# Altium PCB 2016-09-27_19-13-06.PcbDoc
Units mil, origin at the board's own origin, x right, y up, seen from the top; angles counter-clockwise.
Board outline 3075 x 1501 mil, 4 copper layers (Top Layer, MidLayer1, MidLayer2, Bottom Layer); 18 components, 10 nets, 43 pads, 143 vias.
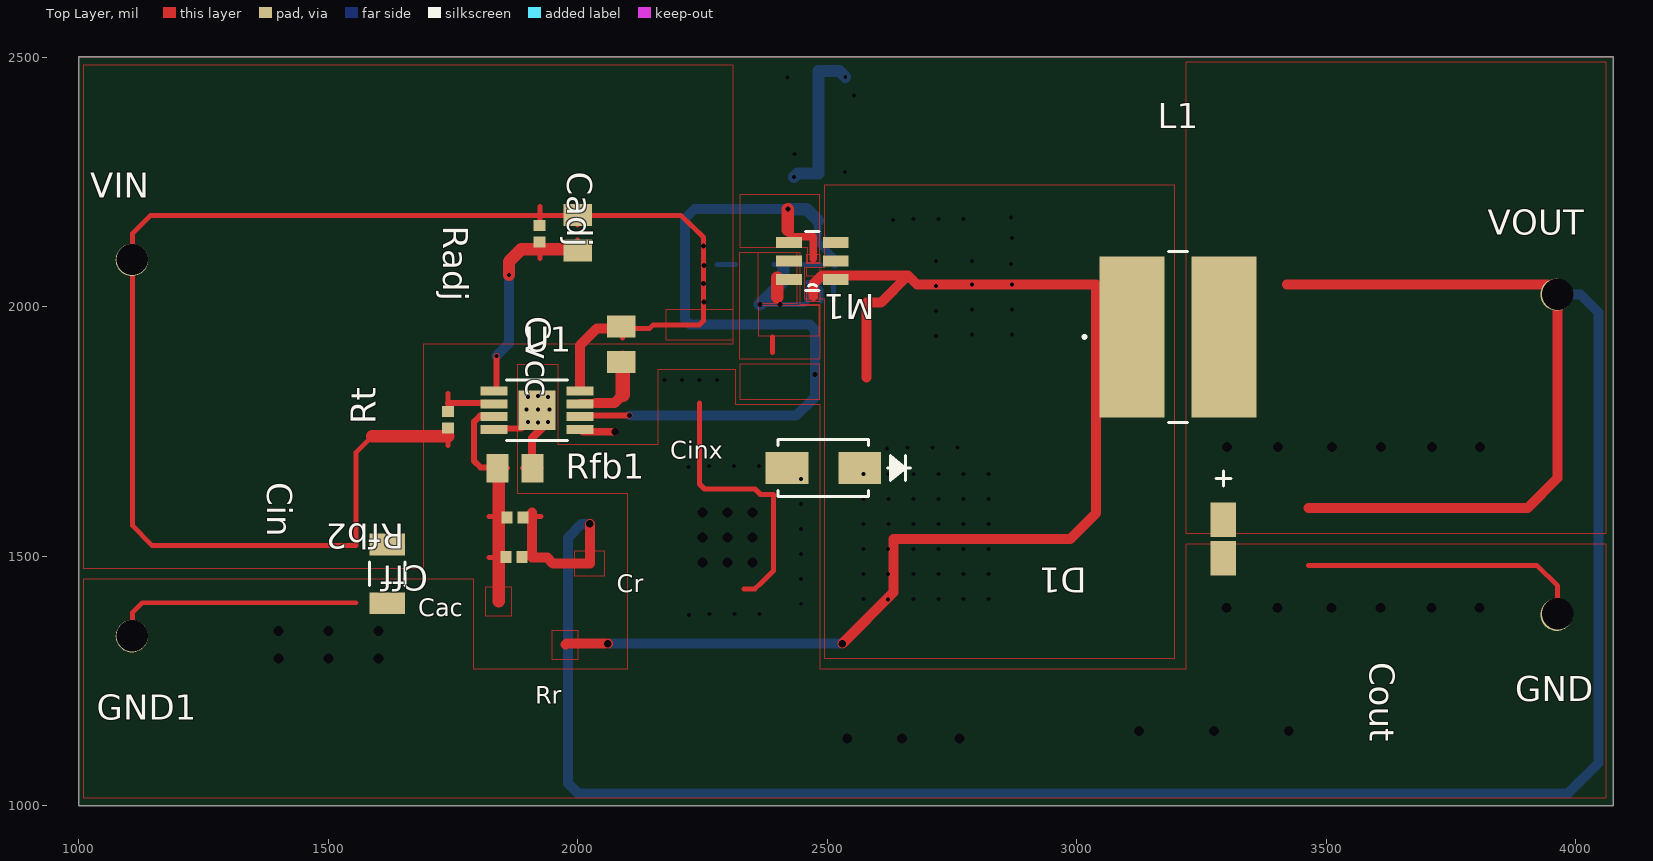
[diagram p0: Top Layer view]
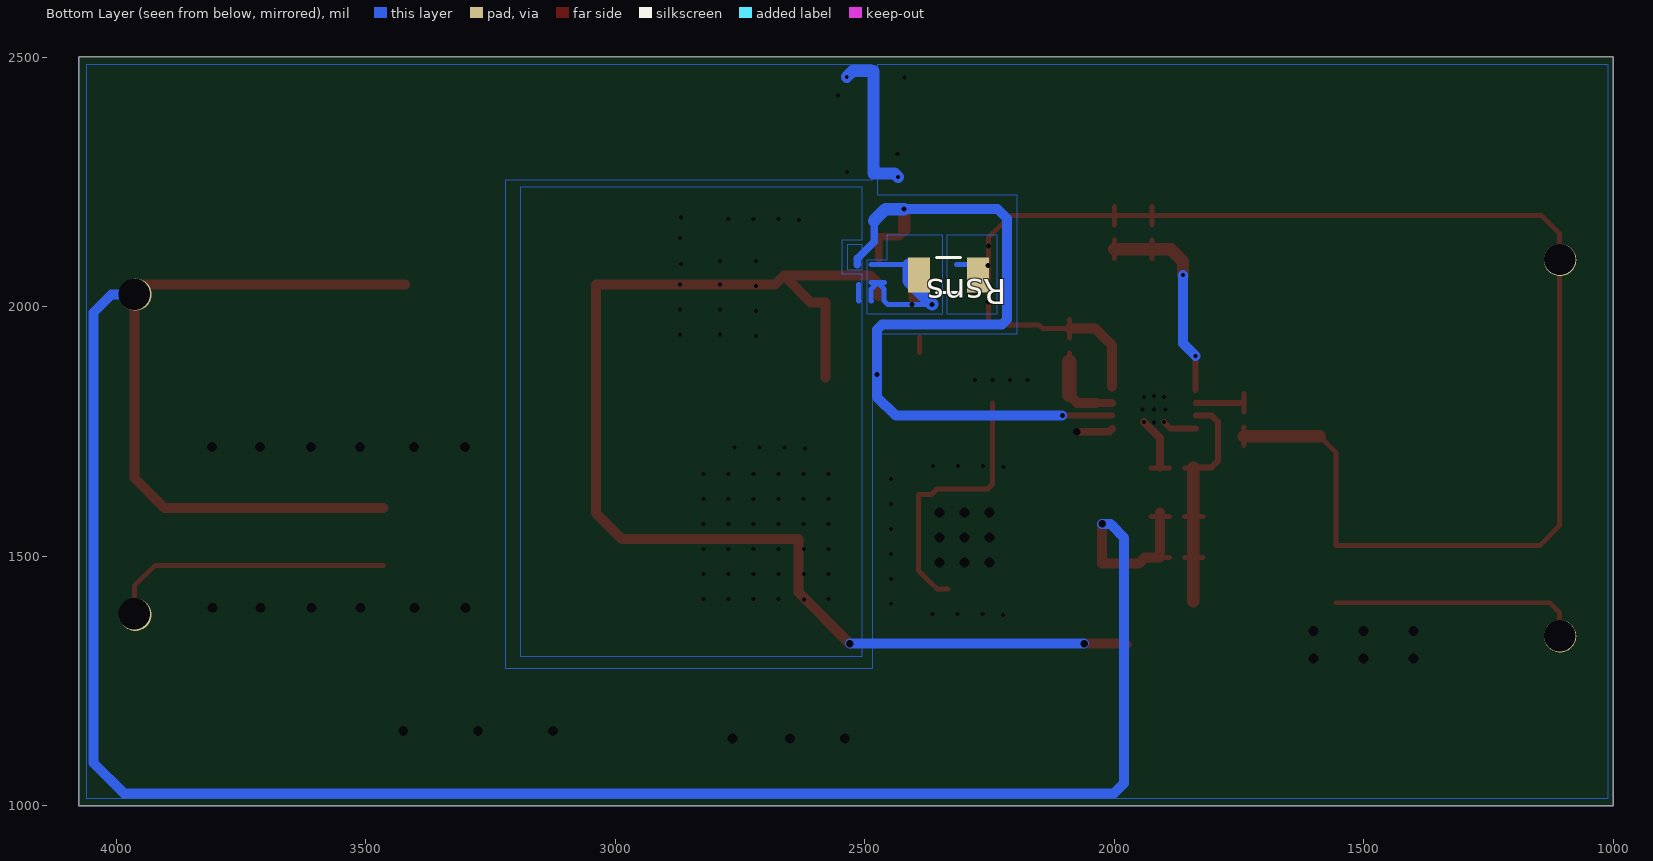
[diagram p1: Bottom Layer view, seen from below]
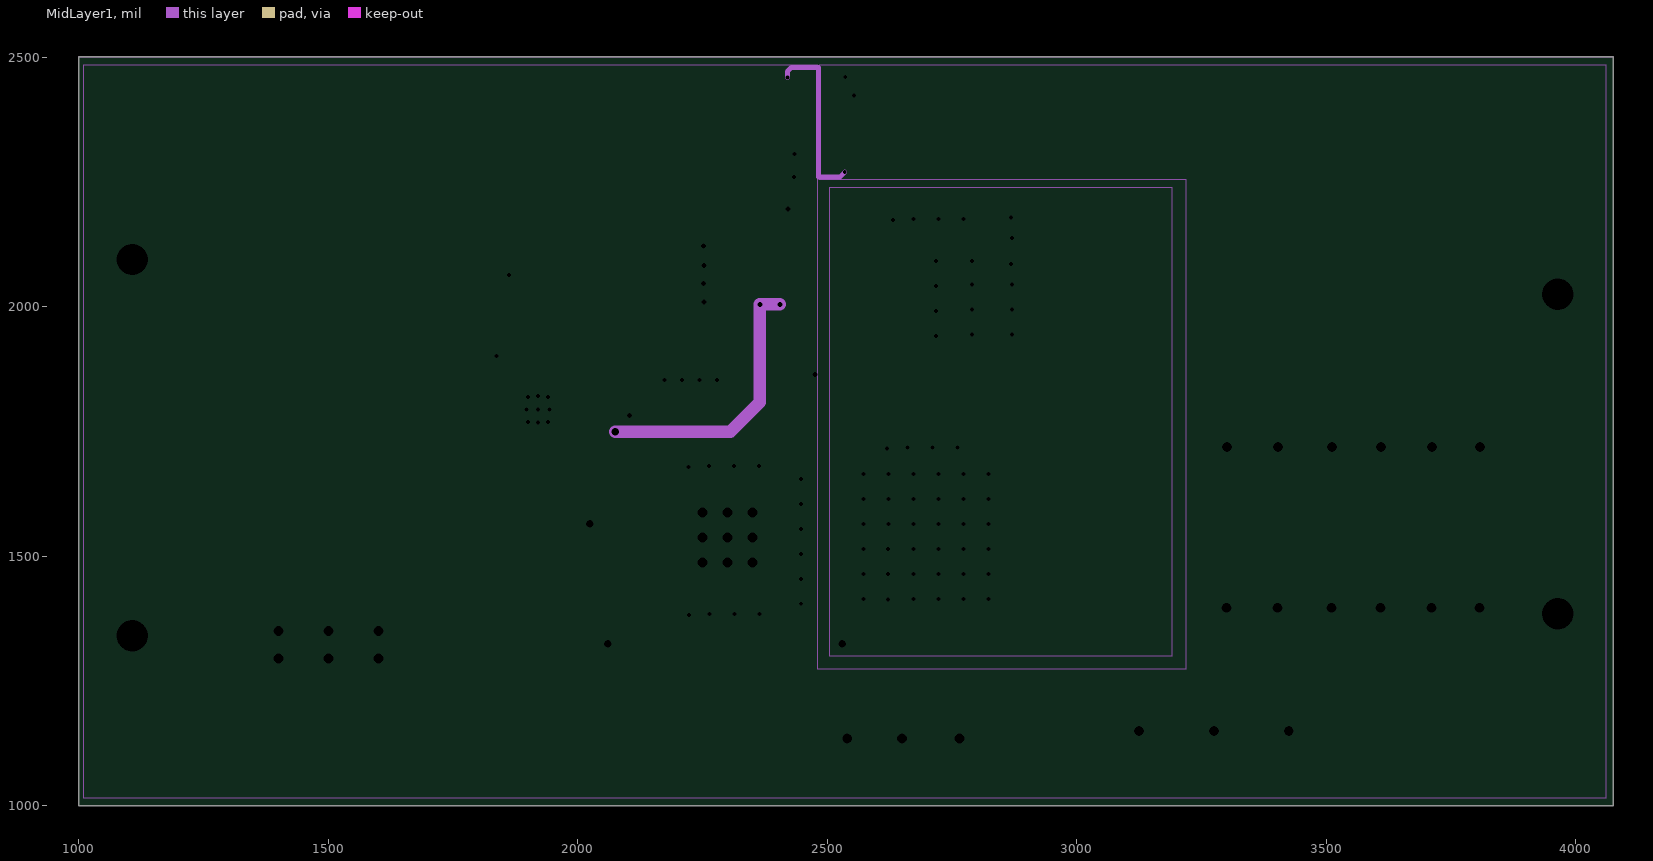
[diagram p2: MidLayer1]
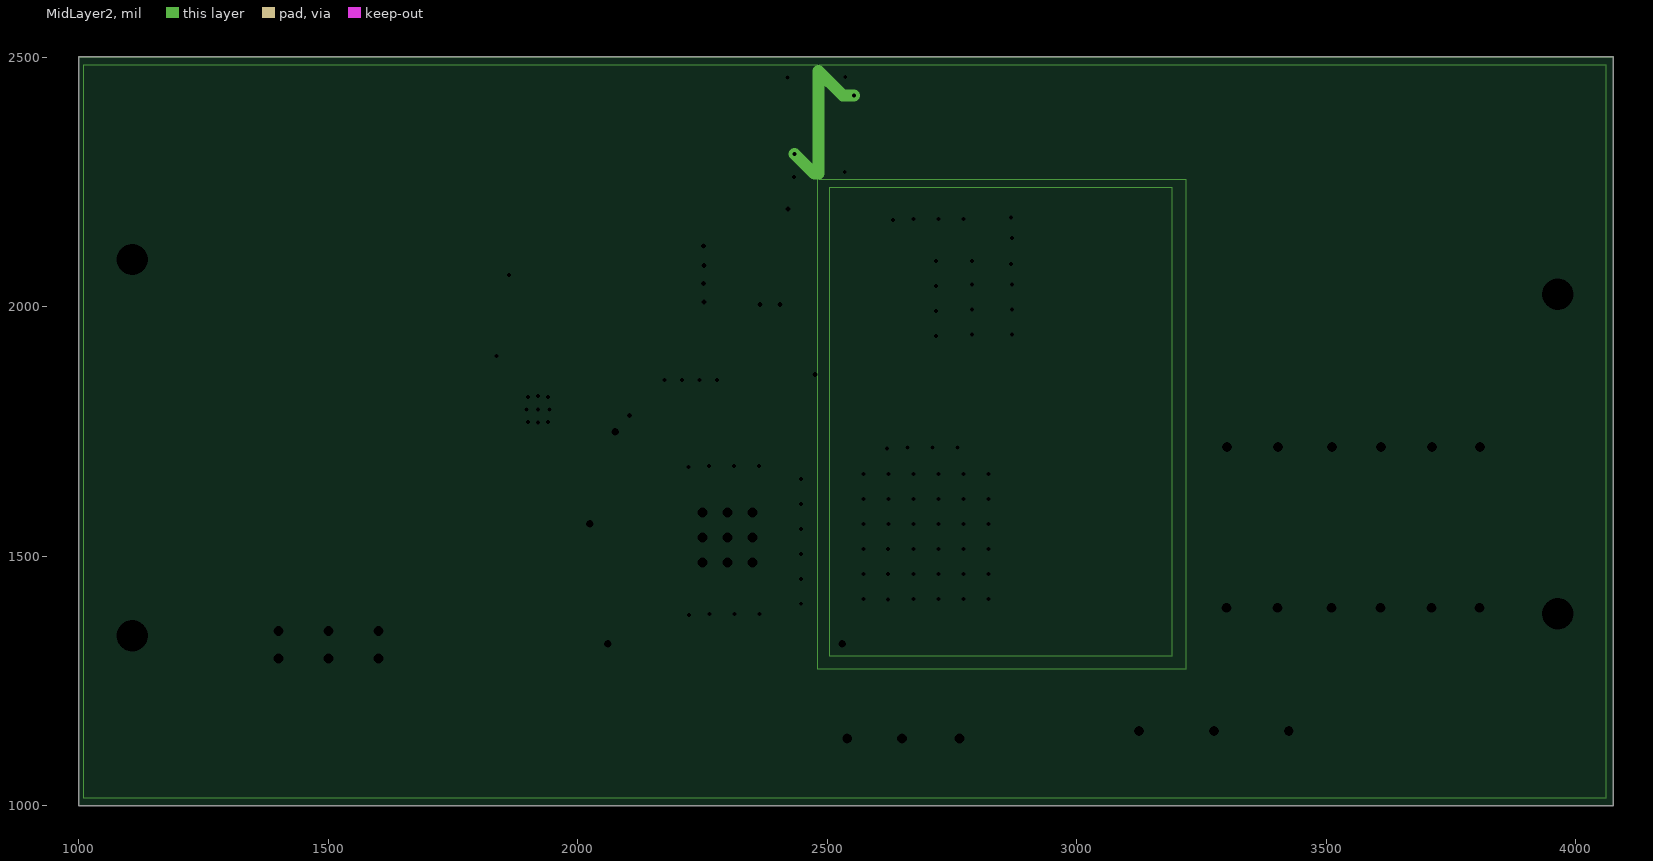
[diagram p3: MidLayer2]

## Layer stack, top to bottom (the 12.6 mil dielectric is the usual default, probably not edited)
Top Layer: signal copper 1.4
Dielectric: core 12.6, FR-4, Dk 4.8
MidLayer1: signal copper 1.4
Dielectric: prepreg 12.6, FR-4, Dk 4.8
MidLayer2: signal copper 1.4
Dielectric: core 12.6, FR-4, Dk 4.8
Bottom Layer: signal copper 1.4

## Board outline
1000,1000 4075,1000 4075,2501 1000,2501

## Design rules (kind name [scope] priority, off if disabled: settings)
PlaneConnect [All] p0: scope1count=1 scope1_0_kind=Board scope1_0_value=Board scope2count=1 scope2_0_kind=Board scope2_0_value=Board commentlength=0 planeconnectstyle=Direct reliefexpansion=20 reliefentries=4 reliefconductorwidth=10 reliefairgap=10
PlaneConnect [All] p1: planeconnectstyle=Direct reliefexpansion=20 reliefentries=4 reliefconductorwidth=10 reliefairgap=10
PolygonConnect [All] p0: scope1count=1 scope1_0_kind=Board scope1_0_value=Board scope2count=1 scope2_0_kind=Board scope2_0_value=Board commentlength=0 connectstyle=Direct reliefconductorwidth=10 reliefentries=4 polygonreliefangle="90 Angle"
PolygonConnect [All] p1: connectstyle=Direct reliefconductorwidth=10 reliefentries=4 polygonreliefangle="90 Angle"

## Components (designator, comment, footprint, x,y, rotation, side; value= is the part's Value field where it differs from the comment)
Cadj "" 0805 2000,2149 r270 top
Cff "" 0402 1872,1499 r180 top
Cin "" 1206_190 1618,1465 r270 top
Cout "" 3216-18 3294,1535 r270 top
Cvcc "" 0805 2087,1925 r270 top
D1 "" SMA 2492,1677 r180 top
GND "" TP-1502 3962,1383 r0 top
GND1 "" TP-1502 1106,1340 r0 top
L1 "" VLP8040 3203,1940 r0 top
M1 "" SOT-23-6 2470,2092 r180 top
Radj "" 0402 1923,2147 r270 top
Rfb1 "" 0805 1874,1677 r0 top
Rfb2 "" 0402 1874,1578 r180 top
Rsns "" 1206 2332,2064 r180 bottom
Rt "" 0402 1740,1774 r90 top
U1 "" MUY08A 1918,1793 r0 top
VIN "" TP-1502 1106,2094 r0 top
VOUT "" TP-1502 3962,2025 r0 top

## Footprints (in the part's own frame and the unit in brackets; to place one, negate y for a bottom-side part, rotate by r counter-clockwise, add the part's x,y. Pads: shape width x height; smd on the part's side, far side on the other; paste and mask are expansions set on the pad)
0402 [mil]
  rect 22x24 smd: 1(-16.5,0) 2(16.5,0)
0805 [mil]
  rect 44x57 smd: 1(-35.5,0) 2(35.5,0)
1206 [mil]
  rect 44x71 smd: 1(59,0) 2(-59,0)
  silkscreen extent -24,-36 24,36
1206_190 [mil]
  rect 44x71 smd: 1(-59,0) 2(59,0)
  silkscreen extent -24,-36 24,36
3216-18 [mil]
  rect 69x51 smd: 1(-38.5,0) 2(38.5,0)
  silkscreen extent -136,-15 -106,15
MUY08A [mil]
  rect 54x18 smd: 1(-86.5,38.39) 2(-86.5,12.8) 3(-86.5,-12.8) 4(-86.5,-38.39) 5(86.5,-38.39) 6(86.5,-12.8) 7(86.5,12.8) 8(86.5,38.39)
  rect 74x79 smd: 9(0,0)
  silkscreen extent -61,-61 61,61
SMA [mil]
  rect 86x64 smd: 1(-73,0) 2(73,0)
  silkscreen extent -174,-58 90,58
SOT-23-6 [mil]
  rect 52x22 smd: 1(-47,37.4) 2(-47,0) 3(-47,-37.4) 4(47,-37.4) 5(47,0) 6(47,37.4)
  silkscreen extent -13,-59 13,59
TP-1502 [mil]
  round 65 / inner round 0 / far side round 65 hole 32: 1(0,0)
VLP8040 [mil]
  rect 130x323 smd: 1(-92.5,0) 2(92.5,0)
  silkscreen extent -190,-172 19,172

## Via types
v1: diameter 0, hole 8, Top Layer to Bottom Layer, 93 vias
v2: diameter 0, hole 20, Top Layer to Bottom Layer, 33 vias
v3: diameter 0, hole 10, Top Layer to Bottom Layer, 9 vias
v4: diameter 0, hole 15, Top Layer to Bottom Layer, 4 vias
v5: diameter 0, hole 63, Top Layer to Bottom Layer, 4 vias

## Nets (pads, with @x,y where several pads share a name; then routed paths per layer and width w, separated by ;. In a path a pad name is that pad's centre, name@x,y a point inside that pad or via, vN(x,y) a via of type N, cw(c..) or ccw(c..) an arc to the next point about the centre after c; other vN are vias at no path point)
0: Cin.2 Cout.2 D1.2 GND1.1 GND.1 Rfb1.2 U1.4 U1.9 | length 2864.1
  Top Layer w10: v5(1107,1341) 1107,1387 1127,1407 1555,1407 ; Rfb1.2@1889,1677.5 Rfb1.2@1926,1677.5 ; 2244,1807 2244,1645 2254,1635 2333,1635 2355,1635 2366,1624 2392,1624 2392,1471 2366,1445 2355,1435 2333,1435 ; 3465,1482 3922,1482 3964,1441 v5(3964,1385)
  Top Layer w12: U1.4@1836,1756 1887,1756 v1(1900,1769)
  Top Layer w16: Rfb1.2@1908,1678 1908,1737 v1(1940,1769)
  MidLayer1 w10: v1(2420,2460) 2420,2472 2428,2480 2482,2480 2482,2260 2525,2260 v1(2535,2270)
  MidLayer2 w24: v1(2434,2307) 2474,2267 2482,2267 2482,2473 2531,2424 v1(2554,2424)
  Bottom Layer w24: v1(2433,2260) 2440,2267 2482,2267 2482,2473 2524,2473 v1(2536,2461)
  other v1: 2223,1382 2264,1384 2314,1384 2364,1384 2447,1405 2447,1455 2447,1505 2447,1555 2447,1605 2447,1655 2222,1679 2263,1681 2313,1681 2363,1681 1920,1768 1897,1794 1920,1794 1943,1794 1900,1819 1940,1819 1920,1821 2174,1854 2209,1854 2244,1854 2279,1854
  other v2: 2540,1135 2650,1135 2765,1135 3125,1150 3275,1150 3425,1150 1400,1295 1500,1295 1600,1295 1400,1350 1500,1350 1600,1350 3300,1397 3402,1397 3511,1397 3609,1397 3711,1397 3807,1397 2250,1488 2300,1488 2350,1488 2250,1538 2300,1538 2350,1538 2250,1588 2300,1588 2350,1588
1: Cff.2 Rfb1.1 Rfb2.2 U1.3 | length 561.4
  Top Layer w10: 1822,1497.5 Cff.2@1859,1497.5 ; 1822,1579.5 Rfb2.2@1859,1579.5 ; Rfb1.1@1822,1677.5 Rfb1.1@1859,1677.5
  Top Layer w12: U1.3@1836,1782 1804,1782 1792,1770 1792,1691 1805,1678 Rfb1.1@1841,1678
  Top Layer w25: 1841,1410 1841,1498 Rfb1.1@1841,1678
2: Rt.2 U1.2 | length 134
  Top Layer w10: Rt.2@1739.5,1789 1739.5,1826 ; 1740,1807 1740,1808
  Top Layer w12: 1740,1807 U1.2@1836,1807
3: Cadj.1 Cin.1 Cvcc.1 Radj.1 Rsns.1 Rt.1 U1.8 VIN.1 | length 3315.7
  Top Layer w10: 1588,1741 1555,1708 1555,1522 1146,1522 1107,1562 v5(1107,2095) 1107,2147 1143,2183 1925,2183 2207,2183 2252,2139 2252,1972 2244,1964 2151,1964 2144,1957 Cvcc.1@2090,1957 ; 1739.5,1722 Rt.1@1739.5,1759 ; Radj.1@1924.5,2164 1924.5,2201 ; Cadj.1@1999.5,2164 Cadj.1@1999.5,2201 ; 2089.5,1938 Cvcc.1@2089.5,1975
  Top Layer w20: U1.8@2004,1840 2004,1923 2038,1957 Cvcc.1@2090,1957
  Top Layer w25: 1588,1741 1740,1741
  Bottom Layer w10: Rsns.1@2279,2085 2316,2085
  other v3: 2253,2010 2252,2047 2253,2083 2252,2122
4: M1.3 U1.6 | length 1702.7
  Top Layer w12: U1.6@2004,1782 v3(2104,1782)
  Top Layer w15: v3(2421,2196) 2421,2149 2423,2149 2431,2141 2447,2141 2446,2141 2472,2141 2472,2097
  Top Layer w25: 2421,2155 v3(2421,2196) 2421,2160
  Bottom Layer w10: 2511,2085 2512,2085
  Bottom Layer w15: 2481,2173 2481,2131 2514,2098 ; 2515,2085 2515,2098
  Bottom Layer w20: v3(2104,1782) 2437,1782 2475,1819 2475,1955 2465,1965 2225,1965 2215,1975 2215,2177 2234,2196 v3(2421,2196)
  Bottom Layer w25: v3(2421,2196) 2458,2196 2481,2173
  other v3: 2475,1865
5: M1.4 Rsns.2 U1.5 | length 1121.1
  Top Layer w10: 2390,1909 2390,1940
  Top Layer w15: U1.5@2004,1756 2010,1750 v4(2075,1750)
  Top Layer w25: 2400,2019 2400,2059
  MidLayer1 w25: v4(2075,1750) 2306,1750 2365,1809 v3(2365,2005) v3(2405,2005)
  Bottom Layer w10: v3(2365,2005) v3(2405,2005) 2454,2005 2461,2012 ; Rsns.2@2393,2085 2430,2085 ; Rsns.2@2412,2085 2461,2085 ; 2460,2012 2461,2012 ; 2460,2048.5 2487,2048.5 ; 2460,2085 2461,2085 ; 2486,2012 2487,2012 2487,2036 2474,2049 2461,2036 2461,2012 ; 2486,2085 2487,2085 2461,2085
  Bottom Layer w25: v3(2365,2005) 2412,2052 Rsns.2@2412,2085
6: Cadj.2 Radj.2 U1.1 | length 490.7
  Top Layer w10: 1924.5,2097 Radj.2@1924.5,2134 ; Cadj.2@1999.5,2097 Cadj.2@1999.5,2134
  Top Layer w12: U1.1@1837,1833 v1(1837,1902)
  Top Layer w25: v1(1862,2064) 1862,2091 1887,2116 1925,2116 Cadj.2@2000,2116
  Bottom Layer w20: v1(1837,1902) 1862,1927 v1(1862,2064)
7: Cvcc.2 U1.7 | length 196
  Top Layer w10: Cvcc.2@2089.5,1871 Cvcc.2@2089.5,1908
  Top Layer w16: U1.7@2004,1807 2036,1807
  Top Layer w20: 2036,1807 2073,1807 2090,1824
  Top Layer w30: 2090,1824 Cvcc.2@2090,1890
8: D1.1 L1.1 M1.1 M1.2 M1.5 M1.6 | length 2587.9
  Top Layer w20: 1975,1323 1977,1325 v4(2060,1325) ; 2472,2022 2472,2046 2489,2063 2662,2063 ; v4(2530,1325) 2633,1428 2633,1533 ; 2579,1859 2579,1909 2579,1959 2579,2009 2608,2009 2662,2063 ; 2633,1535 2735,1535 2987,1535 3039,1587 3039,2045 2680,2045 2662,2063
  Bottom Layer w10: 2511,2012 2512,2012 2512,2045 ; 2511,2044.5 2512,2044.5
  Bottom Layer w20: v4(2060,1325) v4(2530,1325)
  other v1: 2622,1414 2573,1415 2673,1415 2723,1415 2773,1415 2823,1415 2573,1465 2622,1465 2673,1465 2723,1465 2773,1465 2823,1465 2573,1515 2622,1515 2673,1515 2723,1515 2773,1515 2823,1515 2573,1565 2623,1565 2673,1565 2723,1565 2773,1565 2823,1565 2573,1615 2623,1615 2673,1615 2723,1615 2773,1615 2823,1615 2573,1665 2623,1665 2673,1665 2723,1665 2773,1665 2823,1665 2620,1716 2661,1718 2711,1718 2761,1718 2718,1942 2790,1945 2870,1945 2718,1992 2790,1995 2870,1995 2718,2042 2790,2045 2870,2045 2868,2086 2718,2092 2790,2092 2870,2138 2632,2174 2673,2176 2723,2176 2773,2176 2868,2179
9: Cff.1 Cout.1 L1.2 Rfb2.1 VOUT.1 | length 5454.8
  Top Layer w10: Cff.1@1889,1497.5 1926,1497.5 ; Rfb2.1@1889,1579.5 1926,1579.5
  Top Layer w20: 1908,1588 1908,1498 1939,1498 1950,1486 2024,1486 v4(2024,1565) ; 3421,2045 3944,2045 v5(3964,2025) 3964,1657 3904,1597 3465,1597
  Bottom Layer w20: v4(2024,1565) 2007,1565 1980,1537 1980,1045 2000,1025 3985,1025 4046,1086 4046,1989 4010,2025 v5(3964,2025)
  other v2: 3301,1719 3403,1719 3512,1719 3610,1719 3712,1719 3808,1719

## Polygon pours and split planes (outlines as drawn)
8 on Top Layer " " (solid, pour order 0): 2459,2010 2459,2029 2485,2029 2485,2010
8 on Top Layer " " (solid, pour order 1): 2459,2061 2459,2080 2485,2080 2485,2061
4 on Top Layer " " (solid, pour order 2): 2459,2087 2459,2106 2485,2106 2485,2087
5 on Top Layer " " (solid, pour order 3): 2362,2006 2362,2110 2439,2110 2439,2006
5 on Top Layer " " (solid, pour order 4): 2363,1941 2363,2003 2483,2003 2483,1941
3 on Top Layer " " (solid, pour order 5): 2177,1933 2177,1995 2310,1995 2310,1933
8 on Top Layer " " (solid, pour order 7): 1949,1293 1949,1352 2000,1352 2000,1293
9 on Top Layer " " (solid, pour order 9): 1994,1460 1994,1511 2053,1511 2053,1460
1 on Top Layer " " (solid, pour order 11): 1815,1380 1815,1439 1866,1439 1866,1380
3 on Top Layer " " (solid, pour order 12): 1010,2485 2310,2485 2310,1925 1690,1925 1690,1475 1010,1475
9 on Top Layer " " (solid, pour order 13): 4060,2491 4060,1545 3220,1545 3220,2491
4 on Top Layer " " (solid, pour order 14): 2325,2225 2325,2120 2460,2120 2460,2090 2485,2090 2485,2225
5 on Top Layer " " (solid, pour order 15): 2325,2110 2445,2110 2445,2005 2485,2005 2485,1895 2325,1895
8 on Top Layer " " (solid, pour order 16): 3195,2245 3195,1295 2495,1295 2495,2015 2455,2015 2455,2080 2495,2080 2495,2245
4 on Top Layer " " (solid, pour order 17): 2325,1885 2325,1815 2485,1815 2485,1885
0 on Top Layer " " (solid, pour order 24): 1010,1455 1790,1455 1790,1275 2100,1275 2100,1625 1880,1625 1880,1885 1960,1885 1960,1725 2161,1725 2161,1875 2315,1875 2315,1805 2485,1805 2485,1275 3220,1275 3220,1525 4060,1525 4060,1015 1010,1015
8 on Bottom Layer " " (solid, pour order 18): 3190,2240 3190,1300 2505,1300 2505,2065 2545,2065 2545,2135 2505,2135 2505,2240
4 on Bottom Layer " " (solid, pour order 19): 2505,2125 2535,2125 2535,2075 2505,2075
3 on Bottom Layer " " (solid, pour order 20): 2235,1985 2335,1985 2335,2145 2235,2145
5 on Bottom Layer " " (solid, pour order 21): 2495,1985 2495,2095 2455,2095 2455,2145 2345,2145 2345,1985
0 on Bottom Layer " " (solid, pour order 25): 1010,2485 2475,2485 2475,2225 2195,2225 2195,1945 2485,1945 2485,1275 3220,1275 3220,2255 2485,2255 2485,2485 4060,2485 4060,1015 1010,1015
8 on MidLayer1 " " (solid, pour order 22): 2505,1300 2505,2240 3190,2240 3190,1300
8 on MidLayer2 " " (solid, pour order 23): 2505,1300 2505,2240 3190,2240 3190,1300
0 on MidLayer1 " " (solid, pour order 26): 1010,2485 2480,2485 2480,1275 3220,1275 3220,2255 2485,2255 2485,2485 4060,2485 4060,1015 1010,1015
0 on MidLayer2 " " (solid, pour order 27): 1010,2485 2480,2485 2480,1275 3220,1275 3220,2255 2485,2255 2485,2485 4060,2485 4060,1015 1010,1015

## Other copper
Multi-Layer:
  the board outline again, w1

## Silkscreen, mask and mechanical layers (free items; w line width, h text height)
Top Overlay:
  text "Cinx" at 2185,1696 h35
  text "Cr" at 2078,1428 h35
  text "Cac" at 1680,1380 h35
  text "Rr" at 1915,1205 h35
